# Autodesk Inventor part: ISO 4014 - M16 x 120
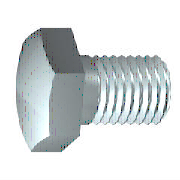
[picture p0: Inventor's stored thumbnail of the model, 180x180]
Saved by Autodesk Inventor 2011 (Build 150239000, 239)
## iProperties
Created: 2009-02
Part Number: ISO 4014 - M16 x 120
Material: Stainless Steel, 440C
Description: Hexagon head bolt - product grades A and B
Document SubType Name: Modeling
Standard: ISO 4014
Designer: 904Chiaki
Standard Revision: Third edition 1999-09-01
Standards Organization: ISO
Language: en-US
Size Designation: M16 x 120
Categories: <MemberInstance><Categories><Category DisplayName="Fasteners" InternalName="e4da775c-781d-43d5-af7c-5136215cf5a6" Mnemonic="FSTN"><Category DisplayName="Bolts"
Density: 7.75 g/cm^3
Mass: 224.623 g
Surface Area: 77.8946 cm^2
Volume: 28.9836 cm^3
IsCustomPart: 0
Author: 904Chiaki
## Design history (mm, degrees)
body "Solid1"
workplane "Work Plane1"
revolve "Body" stored, may be unused: angle "d12" = 90 deg
sketch "Sketch2"
  geometry: L1 (0, 13.856)-(12, 6.928); L2 (12, 6.928)-(12, -6.928); L3 (12, -6.928)-(0, -13.856); L4 (0, -13.856)-(-12, -6.928); L5 (-12, -6.928)-(-12, 6.928); L6 (-12, 6.928)-(0, 13.856); 2 further points
  constraints: 12 end point, 1 coincident, 1 vertical, 11 other
  dimensions: "d11" = 24 distance between parallel lines of L5 L2 (= SW)
extrude "Head" join sketch "Sketch2" distance "d3" = 9.2 (= KOH - SD); taper "d4" = 0 deg
revolve "Chamfer1" stored, may be unused: angle "d21" = 90 deg
feature "Thread" dims "d15" = 38 (= GEL), "d16" = 0
chamfer "Chamfer2" distance "d6" = 1.2269 (= -0.5 x SPD + 0.5 x GD); stored, may be unused: second distance "d7" = 1.227 (computed from GUL), angle "d55" = 45 deg
sketch "Sketch1"
  geometry: L1 (0, 11.245)-(0, 8); L2 (82, 8)-(120, 8); L3 (120, 8)-(120, 0); L4 (120, 0)-(-0.8, 0); L5 (-24.96, 0)-(144.16, 0) reference; L6 (-0.8, 0)-(-0.8, 11.245); L7 (-0.8, 11.245)-(0, 11.245); L8 (82, 8)-(80.773, 8); L9 (80.773, 8)-(0, 8); L10 (0, -2.249)-(0, 13.494) reference
  constraints: 16 end point, 2 collinear, 2 perpendicular, 1 parallel
  dimensions: "d0" = 120 distance between parallel lines of L3 L1 (= NLG); "d1" = 38 distance from line of L2.start L3 (= GEL); "d2" = 16 diameter of L2 L4 (= GD); "d9" = 0.8001 distance between parallel lines of L6 L1 (computed from SD); "d10" = 22.49 diameter of L7 L4 (= SD2); "d13" = 1.227 distance of L2.start L8.end (computed from GAL); "d14" = 16 diameter of L9 L4 (= BDM)
sketch "Sketch4"
  geometry: L1 (-10, 12)-(-10, 13.856); L2 (-10, 13.856)-(-8.928, 13.856); L3 (-8.928, 13.856)-(-10, 12); L4 (-11.84, 0)-(1.04, 0) reference; L5 (-0.8, 13.856)-(-10, 13.856) reference; L6 (-10, 6.928)-(-10, 13.856) reference
  constraints: 6 end point, 2 collinear, 1 perpendicular, 1 vertical
  dimensions: "d5" = 30 deg angle of L3 L1 (= ANG1); "d19" = 24 diameter of L1.start L4 (= SW0)
other parameters: "NLG" = 120 [user parameter; used in 1 equation term], "GD" = 16 (= NND) [user parameter; used in 2 equation terms], "BDM" = 16 (= NND) [user parameter; used in 1 equation term], "KOH" = 10 [user parameter; used in 1 equation term], "GEL" = 38 [user parameter; used in 2 equation terms], "SW" = 24 [user parameter; used in 3 equation terms], "SW0" = 24 (= SW) [user parameter; used in 1 equation term], "SPD" = 13.5462 (= NND - 1.2269 x PTC) [user parameter; used in 1 equation term], "SD2" = 22.49 [user parameter; used in 2 equation terms], "SD" = 0.8 [user parameter; used in 2 equation terms], "ANG1" = 30 deg [user parameter; used in 1 equation term], "GAL" = 1.2269 (= 0.61345 x PTC) [user parameter; used in 1 equation term], "GUL" = 1.2269 (= 0.61345 x PTC) [user parameter; used in 1 equation term], "d8" = 0, "RR" = 0.6 [user parameter], "d57" = 0, "d58" = 0, "TPU" = 5 (computed from PTC) [user parameter], "GD1" = 13.5462 (= THREADDIA - 1.2269 x PTC) [user parameter], "THREADDIA" = 16 [user parameter; used in 1 equation term], "SDH" = 22.49 (= SD2) [user parameter], "TOA" = 30 deg [user parameter], "PTC" = 2 [user parameter; used in 5 equation terms], "NND" = 16 [user parameter; used in 3 equation terms], "E0" = 27.72 (= 1.155 x SW) [user parameter]
